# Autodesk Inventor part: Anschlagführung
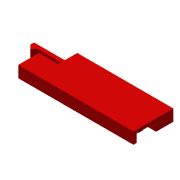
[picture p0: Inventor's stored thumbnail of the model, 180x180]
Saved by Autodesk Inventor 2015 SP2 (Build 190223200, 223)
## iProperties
Created: 2017-07
Material: ABS-rot
Document SubType Name: Modeling
Designer: UR
Density: 1.06 g/cm^3
Appearance: Glatt - weiß(2)
Mass: 3.66898 g
Surface Area: 32.338 cm^2
Volume: 3.4613 cm^3
Part Number: Anschlagführung
Author: UR
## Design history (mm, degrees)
sketch "Skizze2"
  geometry: L1 (0, 14.25)-(-16, 14.25); L2 (-16, 14.25)-(-16, 12.25); L3 (-16, 12.25)-(0, 12.25); L4 (0, 12.25)-(0, 14.25); L5 (-16, 12.25)-(-14, 10.25); L6 (-14, 10.25)-(-12, 12.25); L7 (-14, 10.25)-(-14, 14.25); L8 (0, 0)-(0, 20.75) reference; L9 (0, 11.75)-(50, 11.75) reference; L10 (0, 11.75)-(50, 11.75) reference; 1 further point
  constraints: 14 end point, 3 point on line, 2 parallel, 2 perpendicular, 1 horizontal, 1 other
  dimensions: "d14" = 2 distance between parallel lines of L3 L1; "d16" = 2 distance from line of L5.end L3; "d17" = 90 deg angle of L5 L6; "d46" = 0.5 distance between parallel lines of L9 L3; "d56" = 14 distance from line of L5.end L8
extrude "Grundkörper" new body sketch "Skizze2" distance "d8" = 50; taper "d9" = 0 deg
node "Schiebestange Mittelebene"
extrude "Federzunge mit Rastnase" join sketch "Skizze2" distance "d19" = 5.8; taper "d20" = 0 deg
node "Rastnase Ebene yz"
sketch "Skizze3"
  geometry: L1 (-6, 5)-(-6, 14) reference; L2 (-6, 14)-(0, 14) reference; L3 (0, 14)-(0, -6.75) reference; L4 (0, -6.75)-(-6, -6.75) reference; L5 (-6, -6.75)-(-6, -5) reference; L6 (-6, -5)-(-1.75, -5) reference; L7 (-2, 2)-(-2, 4) reference; L8 (-1.75, 5)-(-6, 5) reference; L9 (-1.75, -5)-(-1.75, -4) reference; L10 (-1.75, -4)-(-2, -4) reference; L11 (-2, -4)-(-2, -2) reference; L12 (-2, -2)-(-1.75, -2) reference; L13 (-1.75, -2)-(-1.75, 2) reference; L14 (-1.75, 2)-(-2, 2) reference; L15 (-2, 4)-(-1.75, 4) reference; L16 (-1.75, 4)-(-1.75, 5) reference; L17 (-1.75, 4)-(0, 4); 1 further point
  constraints: 2 end point, 1 horizontal, 1 point on line
extrude "Überhang" join sketch "Skizze3" distance "d47" = 10; taper "d48" = 0 deg
sketch "Skizze8"
  geometry: L1 (-5.5, 7)-(-45.5, 7); L2 (-45.5, 7)-(-45.5, 2); L3 (-45.5, 2)-(-5.5, 2); L4 (-5.5, 2)-(-5.5, 7); L5 (0, 9)-(0, 0) reference; L6 (0, 9)-(-50, 9) reference; L7 (-50, 0)-(-50, 9) reference; L8 (0, 0)-(-50, 0) reference; L9 (-25.5, 7)-(-25.5, 2); L10 (14, -1.5)-(16, 0.5) reference; L11 (16, 0.5)-(16, 2.5) reference; L12 (16, 2.5)-(0, 2.5) reference; L13 (0, 0.5)-(0, 2.5) reference; L14 (0, 0.5)-(12, 0.5) reference; L15 (12, 0.5)-(14, -1.5) reference; 1 further point
  constraints: 10 end point, 2 midpoint, 2 parallel, 1 horizontal, 1 perpendicular
  dimensions: "d49" = 2 distance between parallel lines of L8 L3; "d50" = 5 distance between parallel lines of L3 L1; "d51" = 40 distance between parallel lines of L2 L4; "d52" = 39.5 distance from line of L10.start L9
extrude "Steckverbindung Nut" cut sketch "Skizze8" distance "d53" = 2.5; taper "d54" = 0 deg
node "Steckverbindung Mitte xz"
node "Steckverbindung Mitte yz"
node "Volumenkörper2"
sketch "Skizze1"
  geometry: L1 (14, -6)-(5, -6); L2 (5, -6)-(5, -1.75); L3 (-6.75, -6)-(-6.75, 0); L4 (-6.75, 0)-(14, 0); L5 (14, 0)-(14, -6); L6 (-5, -1.75)-(-5, -6); L7 (-5, -6)-(-6.75, -6); L8 (0, -1.75)-(0, -6.838); L9 (-2, -1.75)-(-2, -2); L10 (-4, -2)-(-4, -1.75); L11 (4, -1.75)-(4, -2); L12 (2, -2)-(2, -1.75); L13 (5, -1.75)-(4, -1.75); L14 (4, -2)-(2, -2); L15 (-2, -2)-(-4, -2); L16 (2, -1.75)-(-2, -1.75); L17 (-4, -1.75)-(-5, -1.75); L18 (0, -8.206)-(0, 1.368) reference; L19 (-10.9, 0)-(18.15, 0) reference; 1 further point
  constraints: 34 end point, 19 perpendicular, 6 collinear, 6 parallel, 2 vertical, 1 horizontal, 1 midpoint, 2 other
  dimensions: "d7" = 9 distance of L1.start L1.end; "d33" = 1.75 distance between parallel lines of L3 L6; "d34" = 10 distance between parallel lines of L6 L2; "d42" = 4 distance of L12.end L9.start; "d43" = 2 distance of L11.end L12.start; "d44" = 2 distance between parallel lines of L4 L14; "d45" = 0.25 distance between parallel lines of L15 L17
node "Projizierte Kontur3"
node "Projizierte Kontur4"
node "Projizierte Kontur5"
node "Projizierte Kontur6"
other parameters: "d31" = 2, "d55" = 0
